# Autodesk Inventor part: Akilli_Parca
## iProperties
Shininess: 25.0
Length Units: 11269
Angle Units: 11279
Time Units: 11290
Mass Units: 11283
Length Display Precision: 3
Angle Display Precision: 2
Created: 2000-11
Part Number: Akilli_Parca
Material: Aluminum
Document SubType Name: Modeling
Designer: rak
Density: 2.71 g/cm^3
Density: 2.71
Volumn: 0.7623701316578587
Area: 7.420611801966939
PropertySet Name: Model Information
Control State: 0
Master: False
Checked Out: False
Author: rak
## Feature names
1. Revolution1
2. Hole1
